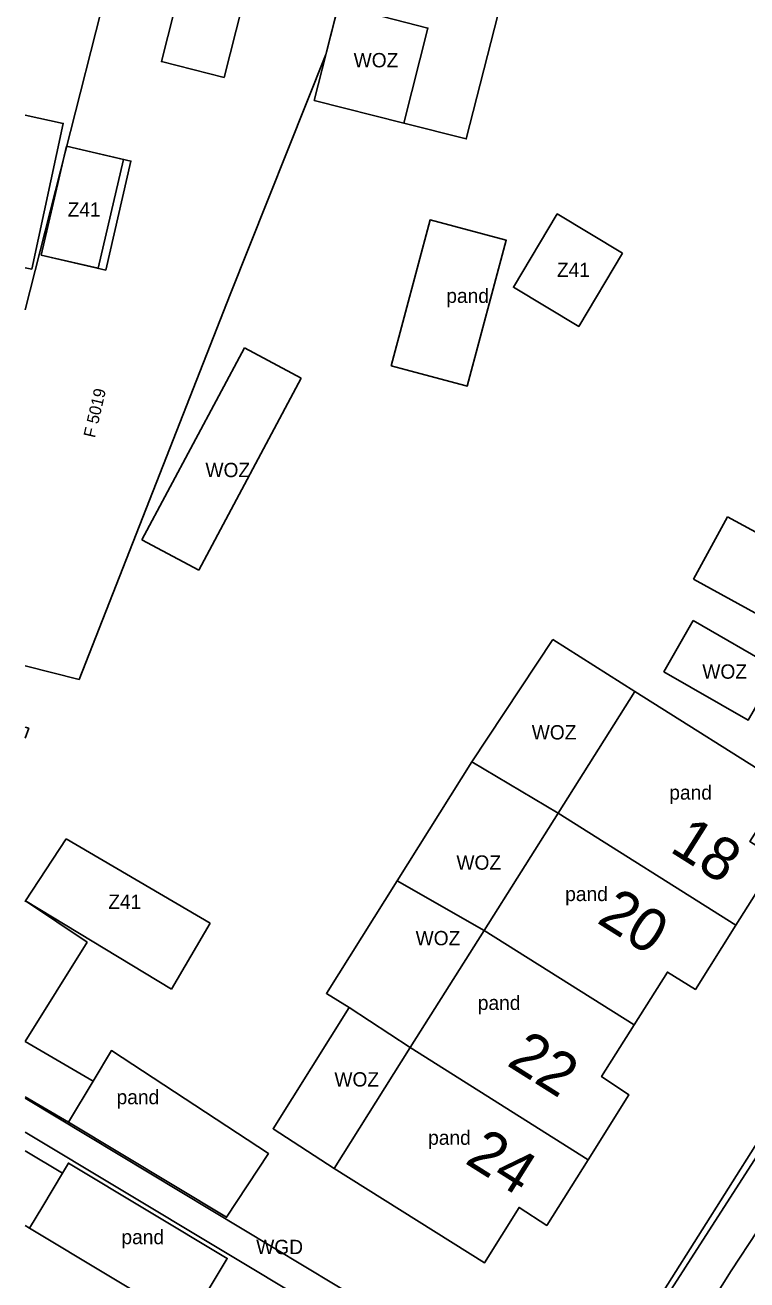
# Model space of a CAD drawing. Extents: x 198240 to 198429, y 356553 to 356721.
# Drawn here: x 198239.8 to 198270, y 356629.6 to 356682.2 of the extents above; entities that cross this region are included whole.
import ezdxf

# ---------------------------------------------------------------- set-up
doc = ezdxf.new("R2010")
doc.units = 0
for name, color, linetype in [('(presentatie) Code GPNDDECOM (lijn of vlak) (zonder attributen) niet in de presentatietabel', 7, 'Continuous'), ('bijgebouw', 7, 'Continuous'), ('Grens maaiveld', 7, 'Continuous'), ('grens WOZ object', 7, 'Continuous'), ('hoofdgebouw', 7, 'Continuous'), ('huisnummerreeks BGT', 7, 'Continuous'), ('identificerend kenmerkpunt bijpand', 7, 'Continuous'), ('identificerend kenmerkpunt pand', 7, 'Continuous'), ('identificerend kenmerkpunt WOZ object', 7, 'Continuous'), ('kant verharding', 7, 'Continuous'), ('Perceelnummer', 7, 'Continuous'), ('perceelsgrens_definitief', 7, 'Continuous'), ('tussenmuur', 7, 'Continuous'), ('wegdeel kenmerkpunt', 7, 'Continuous')]:
    doc.layers.add(name, color=color, linetype=linetype)

msp = doc.modelspace()

# ---------------------------------------------------------------- linework, layer by layer
at = {"layer": '(presentatie) Code GPNDDECOM (lijn of vlak) (zonder attributen) niet in de presentatietabel'}
msp.add_line((198242.632, 356637.944), (198239.791, 356639.605), dxfattribs=at)
for points in [[(198241.52, 356677.116), (198244.22, 356676.491), (198243.163, 356671.929), (198240.463, 356672.554)], [(198241.601, 356636.229), (198239.787, 356637.289)]]:
    msp.add_lwpolyline(points, dxfattribs=at)
at = {"layer": 'bijgebouw'}
for p, q in [((198255.116, 356667.917), (198255.745, 356667.749)), ((198255.745, 356667.749), (198258.199, 356667.093)), ((198239.937, 356652.728), (198239.787, 356652.782)), ((198239.787, 356652.313), (198239.937, 356652.728)), ((198239.806, 356645.506), (198241.507, 356648.1)), ((198241.507, 356648.1), (198247.541, 356644.559)), ((198245.923, 356641.8), (198239.806, 356645.506)), ((198247.541, 356644.559), (198245.923, 356641.8)), ((198241.348, 356634.089), (198240.529, 356632.716)), ((198239.968, 356631.79), (198240.529, 356632.716))]:
    msp.add_line(p, q, dxfattribs=at)
for points in [[(198239.787, 356672.025), (198240.063, 356671.965), (198241.386, 356678.072), (198239.787, 356678.421)], [(198258.199, 356667.093), (198258.306, 356667.065), (198259.938, 356673.179), (198256.748, 356674.031), (198255.116, 356667.917)], [(198264.814, 356672.641), (198262.973, 356669.567), (198260.237, 356671.205), (198262.078, 356674.279), (198264.814, 356672.641)], [(198241.348, 356634.089), (198241.602, 356634.513), (198248.255, 356630.521), (198246.617, 356627.795), (198239.968, 356631.79)]]:
    msp.add_lwpolyline(points, dxfattribs=at)
at = {"layer": 'Grens maaiveld'}
for p, q in [((198241.52, 356677.116), (198240.463, 356672.554)), ((198242.632, 356637.944), (198241.601, 356636.229))]:
    msp.add_line(p, q, dxfattribs=at)
for points in [[(198241.52, 356677.116), (198243.911, 356676.563), (198242.854, 356672.001), (198240.463, 356672.554)], [(198242.632, 356637.944), (198243.404, 356639.227), (198249.98, 356634.91), (198248.229, 356632.243), (198241.601, 356636.229)]]:
    msp.add_lwpolyline(points, dxfattribs=at)
at = {"layer": 'grens WOZ object'}
for p, q in [((198252.91, 356683.019), (198251.898, 356679.037)), ((198251.898, 356679.037), (198255.645, 356678.084)), ((198248.974, 356668.663), (198244.683, 356660.622)), ((198251.35, 356667.395), (198248.974, 356668.663)), ((198247.059, 356659.354), (198251.35, 356667.395)), ((198269.211, 356661.592), (198267.776, 356658.973)), ((198273.408, 356659.291), (198269.211, 356661.592)), ((198244.683, 356660.622), (198247.059, 356659.354)), ((198267.776, 356658.973), (198271.973, 356656.672)), ((198258.492, 356651.319), (198261.884, 356656.445)), ((198261.884, 356656.445), (198265.328, 356654.273)), ((198265.328, 356654.273), (198262.114, 356649.176)), ((198255.371, 356646.344), (198258.492, 356651.319)), ((198258.492, 356651.319), (198262.114, 356649.176)), ((198259.017, 356644.263), (198255.371, 356646.344)), ((198239.806, 356645.506), (198242.384, 356643.769)), ((198242.384, 356643.769), (198239.791, 356639.605)), ((198255.919, 356639.35), (198253.366, 356641.035)), ((198241.348, 356634.089), (198239.787, 356635.025)), ((198239.968, 356631.79), (198239.787, 356631.902))]:
    msp.add_line(p, q, dxfattribs=at)
for points in [[(198267.769, 356657.243), (198271.304, 356655.213), (198270.074, 356653.07), (198266.539, 356655.1), (198267.769, 356657.243)], [(198253.366, 356641.035), (198252.409, 356641.624), (198255.371, 356646.344)], [(198239.787, 356645.459), (198239.806, 356645.506)], [(198252.731, 356634.294), (198250.171, 356635.95), (198253.366, 356641.035)], [(198239.787, 356639.607), (198239.791, 356639.605)]]:
    msp.add_lwpolyline(points, dxfattribs=at)
at = {"layer": 'hoofdgebouw'}
for p, q in [((198262.114, 356649.176), (198259.017, 356644.263)), ((198259.017, 356644.263), (198255.919, 356639.35)), ((198255.919, 356639.35), (198252.731, 356634.294))]:
    msp.add_line(p, q, dxfattribs=at)
for points in [[(198252.91, 356683.019), (198249.136, 356683.978), (198248.124, 356679.996), (198245.498, 356680.66), (198248.431, 356692.255), (198254.831, 356690.63)], [(198255.645, 356678.084), (198258.264, 356677.418), (198261.225, 356689.006), (198254.831, 356690.63)], [(198252.91, 356683.019), (198256.657, 356682.067), (198255.645, 356678.084)], [(198269.556, 356644.485), (198271.294, 356647.246), (198270.143, 356647.981), (198271.619, 356650.308), (198265.328, 356654.273), (198262.114, 356649.176)], [(198265.298, 356640.304), (198266.691, 356642.515), (198267.861, 356641.791), (198269.556, 356644.485)], [(198263.366, 356634.656), (198265.074, 356637.37), (198263.935, 356638.141), (198265.298, 356640.304)], [(198252.731, 356634.294), (198259.022, 356630.329), (198260.473, 356632.659), (198261.634, 356631.905), (198263.366, 356634.656)]]:
    msp.add_lwpolyline(points, dxfattribs=at)
at = {"layer": 'kant verharding'}
for points in [[(198298.672, 356681.879), (198281.729, 356652.893), (198280.805, 356651.439), (198272.725, 356638.444), (198270.553, 356635.006), (198264.327, 356625.306), (198262.967, 356623.203)], [(198262.967, 356623.203), (198256.774, 356627.2), (198256.672, 356627.069), (198239.787, 356637.236)], [(198239.787, 356635.812), (198256.01, 356626.063), (198256.042, 356626.133), (198262.254, 356622.101)], [(198265.95, 356624.757), (198268.291, 356628.312), (198269.36, 356629.996), (198270.462, 356631.678), (198272.546, 356634.962), (198277.462, 356631.806)]]:
    msp.add_lwpolyline(points, dxfattribs=at)
at = {"layer": 'perceelsgrens_definitief'}
for points in [[(198239.787, 356670.263), (198246.545, 356696.869)], [(198252.904, 356682.997), (198252.378, 356680.96)], [(198243.211, 356592.912), (198264.167, 356625.417), (198275.594, 356643.523), (198286.547, 356661.91), (198298.205, 356681.89)], [(198252.378, 356680.96), (198248.376, 356670.904)], [(198248.376, 356670.904), (198242.05, 356654.77)], [(198242.05, 356654.77), (198239.787, 356655.348)]]:
    msp.add_lwpolyline(points, dxfattribs=at)
at = {"layer": 'tussenmuur'}
for p, q in [((198269.556, 356644.485), (198262.114, 356649.176)), ((198259.017, 356644.263), (198265.298, 356640.304)), ((198263.366, 356634.656), (198255.919, 356639.35))]:
    msp.add_line(p, q, dxfattribs=at)

# ---------------------------------------------------------------- texts
at = {"layer": 'huisnummerreeks BGT'}
for s, p in [('18', (198266.735, 356647.594)), ('20', (198263.683, 356644.612)), ('22', (198259.913, 356638.637)), ('24', (198258.157, 356634.538))]:
    msp.add_text(s, height=1.8, rotation=327.8, dxfattribs=at).set_placement(p)
at = {"layer": 'identificerend kenmerkpunt bijpand'}
for s, p in [('Z41', (198241.568, 356674.164)), ('Z41', (198262.062, 356671.639)), ('pand', (198257.428, 356670.55)), ('Z41', (198243.27, 356645.165)), ('pand', (198243.618, 356636.98)), ('pand', (198243.823, 356631.117))]:
    msp.add_text(s, height=0.6, dxfattribs=at).set_placement(p)
at = {"layer": 'identificerend kenmerkpunt pand'}
for p in [(198266.768, 356649.74), (198262.408, 356645.49), (198258.748, 356640.93), (198256.668, 356635.28)]:
    msp.add_text('pand', height=0.6, dxfattribs=at).set_placement(p)
at = {"layer": 'identificerend kenmerkpunt WOZ object'}
for p in [(198253.547, 356680.42), (198247.341, 356663.251), (198268.151, 356654.807), (198261.007, 356652.261), (198257.852, 356646.805), (198256.143, 356643.639), (198252.741, 356637.721)]:
    msp.add_text('WOZ', height=0.6, dxfattribs=at).set_placement(p)
at = {"layer": 'Perceelnummer'}
msp.add_text('F 5019', height=0.5, rotation=77, dxfattribs=at).set_placement((198242.712, 356664.872))
at = {"layer": 'wegdeel kenmerkpunt'}
msp.add_text('WGD', height=0.6, dxfattribs=at).set_placement((198249.467, 356630.7))

doc.saveas('drawing.dxf')
